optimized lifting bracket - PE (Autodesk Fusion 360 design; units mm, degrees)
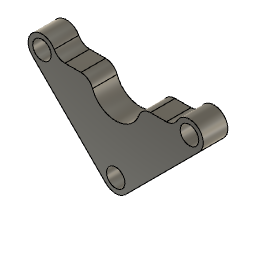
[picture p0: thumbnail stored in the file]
sketch "Sketch1" plane through (0, 0, 0) normal (0, 1, 0) x axis (1, 0, 0)
  line L1 (-12.7, 0) -> (-30.9563, 0)
  line L2 (30.9563, 0) -> (12.7, 0)
  line L3 (43.1514, 5.0514) -> (5.0514, 43.1514)
  line L4 (-5.0514, 43.1514) -> (-43.1514, 5.0514)
  circle C1 centre (0, 0) radius 12.7
  circle C2 centre (-38.1, 0) radius 7.1437
  circle C3 centre (-38.1, 0) radius 4.7625
  circle C4 centre (0, 38.1) radius 7.1437
  circle C5 centre (0, 38.1) radius 4.7625
  circle C6 centre (38.1, 0) radius 7.1437
  circle C7 centre (38.1, 0) radius 4.7625
  point P1 (0, 0)
  point P2 (0, 0)
  point P3 (-38.1, 0)
  point P9 (-30.9563, 0)
  point P10 (-12.7, 0)
  point P11 (12.7, 0)
  point P12 (30.9563, 0)
  point P13 (5.0514, 43.1514)
  point P14 (43.1514, 5.0514)
  point P15 (-43.1514, 5.0514)
  point P16 (-5.0514, 43.1514)
  coincident P1 P2
  concentric C2 C3
  horizontal P2 P3
  coincident C2 P9
  coincident C1 P10
  horizontal L1
  coincident C1 P11
  coincident C6 P12
  parallel L1 L2
  coincident C4 P13
  coincident C6 P14
  tangent C6 L3
  coincident C2 P15
  coincident C4 P16
  tangent C4 L4
  tangent C2 L4
  tangent C4 L3
  coincident P1 L1
  coincident P1 L2
  dimension "d1" diameter C1 = 25.4
  dimension "d2" diameter C3 = 9.525
  dimension "d3" diameter C2 = 14.2875
  dimension "d4" distance P2 P3 = 38.1
  dimension "d6" C-Pattern1-Angle = -180
extrude "Extrude1" new body sketch "Sketch1" distance 12.7
fillet "Fillet1" radius 6.35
